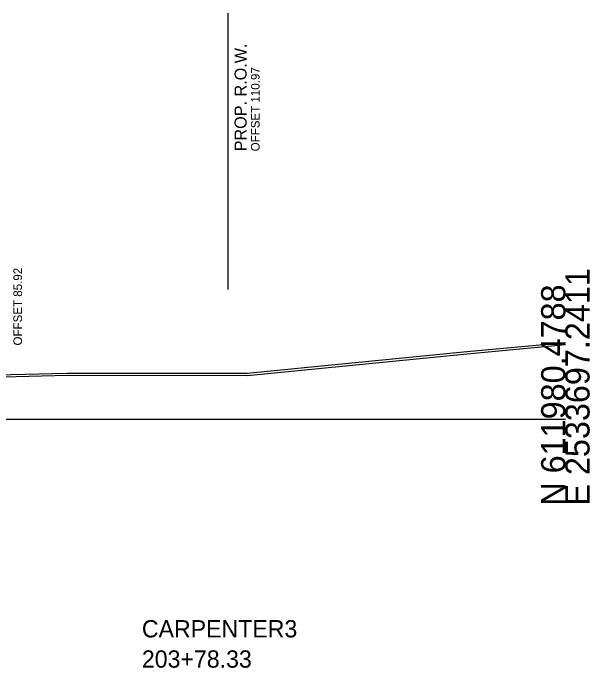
# Model space of a CAD drawing. Extents: x -120 to 2876, y -25 to 8560.
# Drawn here: x 236.1 to 302.8, y 6971.2 to 7047 of the extents above; entities that cross this region are included whole.
import ezdxf

# ---------------------------------------------------------------- set-up
doc = ezdxf.new("R2010")
doc.units = 0
for name, color, linetype in [('DESIGN - ROW - Right-of-Way and Easement Labels', 7, 'Continuous'), ('DESIGN - ROW - Right-of-Way Linework', 7, 'Continuous'), ('DESIGN - SHEET - Light Grid', 7, 'Continuous'), ('DESIGN - TYPICAL - Slope Tie Text', 7, 'Continuous'), ('DESIGN - TYPICAL - Warning Text', 7, 'Continuous'), ('SURVEY - GROUND - Bottom of Topsoil Layer', 7, 'Continuous'), ('SURVEY - GROUND - Top of Ground', 7, 'Continuous')]:
    doc.layers.add(name, color=color, linetype=linetype)

msp = doc.modelspace()

# ---------------------------------------------------------------- linework, layer by layer
at = {"layer": 'DESIGN - ROW - Right-of-Way Linework'}
msp.add_line((260.972, 7015.014), (260.972, 7047.014), dxfattribs=at)
at = {"layer": 'DESIGN - SHEET - Light Grid'}
msp.add_line((150, 7000), (300, 7000), dxfattribs=at)
at = {"layer": 'SURVEY - GROUND - Bottom of Topsoil Layer'}
msp.add_lwpolyline([(182.167, 7013.44), (191.266, 7007.68), (202.834, 7001.374), (206.299, 7001.36), (209.295, 7001.212), (210.447, 7002.12), (212.918, 7003.969), (224.58, 7004.655), (242.336, 7005.097), (263.207, 7005.077), (288.629, 7007.591), (300.023, 7008.649)], dxfattribs=at)
at = {"layer": 'SURVEY - GROUND - Top of Ground'}
msp.add_lwpolyline([(172.346, 7014.322), (174.167, 7014.24), (178.554, 7014.044), (179.018, 7013.992), (180.567, 7013.826), (182.179, 7013.727), (191.393, 7007.895), (202.898, 7001.623), (206.305, 7001.61), (209.214, 7001.466), (210.294, 7002.318), (212.828, 7004.214), (224.57, 7004.905), (242.333, 7005.347), (263.195, 7005.327), (288.605, 7007.839), (300, 7008.898)], dxfattribs=at)

# ---------------------------------------------------------------- texts
at = {"layer": 'DESIGN - ROW - Right-of-Way and Easement Labels'}
for s, height, p in [('PROP. R.O.W.', 1.4, (263.122, 7031.014)), ('OFFSET 110.97', 1, (264.622, 7031.014))]:
    msp.add_text(s, height=height, rotation=90, dxfattribs=at).set_placement(p)
at = {"layer": 'DESIGN - SHEET - Light Grid'}
for s, p in [('E 2533697.2411', (302.8, 6990)), ('N 611980.4788', (300, 6990))]:
    msp.add_text(s, height=2.8, rotation=90, dxfattribs=at).set_placement(p)
at = {"layer": 'DESIGN - TYPICAL - Slope Tie Text'}
msp.add_text('OFFSET 85.92', height=1, rotation=90, dxfattribs=at).set_placement((237.133, 7008.538))
at = {"layer": 'DESIGN - TYPICAL - Warning Text'}
for s, p in [('CARPENTER3', (251, 6974.75)), ('203+78.33', (251, 6971.25))]:
    msp.add_text(s, height=2, dxfattribs=at).set_placement(p)

doc.saveas('drawing.dxf')
